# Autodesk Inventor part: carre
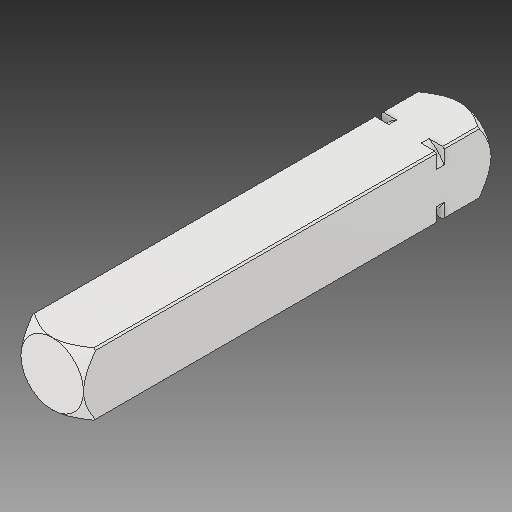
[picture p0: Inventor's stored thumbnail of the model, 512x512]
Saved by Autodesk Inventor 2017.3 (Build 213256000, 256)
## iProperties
Created: 2002-03
Part Number: carre
Material: Générique
Document SubType Name: Modeling
Designer: ficho
Density: 1 g/cm^3
Appearance: Par défaut
Author: ficho
Sending System: SolidWorks 2009
Last Author: christophe
Last Saved: 2011-01-23
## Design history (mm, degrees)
feature "Enlèv. mat.-Extru.4"
node "Solide1"
